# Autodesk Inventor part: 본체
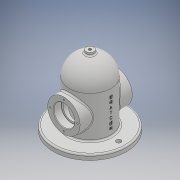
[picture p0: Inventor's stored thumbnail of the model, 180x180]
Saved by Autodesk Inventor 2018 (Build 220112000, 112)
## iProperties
Created: 2019-11
Part Number: 본체
Material: 일반
Document SubType Name: Modeling
Designer: USER
Density: 1 g/cm^3
Appearance: 기본값
Author: USER
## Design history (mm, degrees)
sketch "스케치3"
  geometry: C1 r 31 at (0, 0); 1 further point
  constraints: 1 centre point, 1 coincident
  dimensions: "d3" = 62 diameter of C1
extrude "돌출2" new body sketch "스케치3" stored distance "d4" = 100; taper "d5" = 0 deg
node "작업 평면1"
sketch "스케치5"
  geometry: C1 r 70 at (0, 0); 1 further point
  constraints: 1 centre point, 1 coincident
  dimensions: "d7" = 140 diameter of C1
extrude "돌출3" join sketch "스케치5" distance "d8" = 10; taper "d9" = 0 deg
sketch "스케치6"
  geometry: L1 (70, -40)-(-70, -40) reference; L2 (0, -40)-(-40, -40); L3 (-40, -40)-(-40, 40); L4 (-40, 40)-(0, 40); L5 (0, 40)-(0, -40); L6 (0, 40)-(0, 80); L7 (0, 40)-(-40, 40); L8 (0, 67.168)-(0, -67.168); 2 further points
  constraints: 14 end point, 3 midpoint, 2 horizontal, 2 parallel, 2 vertical, 1 perpendicular
  dimensions: "d10" = 80 distance of L2.end L3.end; "d11" = 40 distance of L3.end L4.end
revolve "회전1" sketch "스케치6" stored, may be unused: angle "d15" = 90 deg
sketch "스케치7"
  geometry: L1 (40, 40)-(-40, 40) reference; L2 (0, 82.045)-(0, -82.045); L3 (0, 40)-(-40, 40); L4 (0, 40)-(0, 80); A1 r 40 centre (0, 40) between (0, 80) and (-40, 40); 2 further points
  constraints: 6 end point, 2 midpoint, 2 point on circle, 2 point on line, 2 vertical, 1 centre point, 1 coincident, 1 horizontal
revolve "회전2" sketch "스케치7" stored, may be unused: angle "d16" = 90 deg
node "작업 평면2"
sketch "스케치8"
  geometry: C1 r 40 at (0, 0) reference; C2 r 7.5 at (0, 0); 1 further point
  constraints: 1 centre point, 1 coincident
  dimensions: "d18" = 15 diameter of C2
extrude "돌출4" join sketch "스케치8" stored distance "d19" = 10; taper "d20" = 0 deg
sketch "스케치9"
  geometry: C1 r 16.5 at (0, 0); 1 further point
  constraints: 1 centre point, 1 coincident
  dimensions: "d21" = 33 diameter of C1
extrude "돌출5" cut sketch "스케치9" extent not by distance; stored distance "d22" = 10; taper "d23" = 0 deg
sketch "스케치10"
  geometry: C1 r 20 at (0, 0); 1 further point
  constraints: 1 centre point, 1 coincident
  dimensions: "d24" = 40 diameter of C1
extrude "돌출6" cut sketch "스케치10" distance "d25" = 15; taper "d26" = 0 deg
sketch "스케치12"
  geometry: L1 (0, 40)-(-30, 40); L2 (-30, 40)-(-30, -50); L3 (-30, -50)-(0, -50); L4 (0, -50)-(0, 40); L5 (0, 126.817)-(0, -126.817); L6 (-70, -50)-(70, -50) reference; 2 further points
  constraints: 10 end point, 2 midpoint, 2 parallel, 1 coincident, 1 horizontal, 1 perpendicular, 1 vertical
  dimensions: "d37" = 30 distance of L1.start L1.end; "d38" = 90 distance of L1.end L2.end
revolve "회전3" sketch "스케치12" stored, may be unused: angle "d39" = 90 deg
sketch "스케치13"
  geometry: L1 (30, 40)-(-30, 40) reference; L2 (0, 40)-(0, 70); L3 (0, 40)-(-30, 40); L4 (0, 70)-(0, 40); L5 (0, 40)-(-30, 40); L6 (0, 99.673)-(0, -99.673); A1 r 30 centre (0, 40) between (0, 70) and (-30, 40); 2 further points
  constraints: 10 end point, 2 midpoint, 2 point on circle, 1 centre point, 1 coincident, 1 vertical
  dimensions: "d40" = 90 deg angle of L2 L3
revolve "회전4" sketch "스케치13" stored, may be unused: angle "d41" = 90 deg
sketch "스케치15"
  geometry: C1 r 7.5 at (0, 0) reference; C2 r 7.5 at (0, 0) reference; 2 further points
  constraints: 1 coincident
hole "구멍1" sketch "스케치15" at (0, 0) diameter "d42" = 5.188; stored, may be unused: countersink angle "d46" = 90 deg, drill point angle "d48" = 118 deg; dims "d43" = 30, "d44" = 4, "d45" = 2, "d47" = 30
sketch "스케치16"
  geometry: 2 further points
  constraints: 1 vertical alignment
  dimensions: "d49" = 26 distance of point (0, 0) point (0, 26)
hole "구멍2" sketch "스케치16" at (0, 26) diameter "d50" = 3.242; stored, may be unused: countersink angle "d54" = 90 deg, drill point angle "d56" = 118 deg; dims "d51" = 8, "d52" = 4, "d53" = 2, "d55" = 10
sketch "스케치17"
  geometry: C1 r 55 at (0, 0); C2 r 4.5 at (-55, 0); C3 r 4.5 at (55, 0); 1 further point
  constraints: 3 centre point, 2 horizontal alignment, 1 coincident
  dimensions: "d60" = 110 diameter of C1; "d61" = 9 diameter of C2; "d62" = 9 diameter of C3; "d63" = 55 distance of point (0, 0) C2.centre; "d64" = 55 distance of point (0, 0) C3.centre
extrude "돌출7" cut sketch "스케치17" distance "d65" = 15; taper "d66" = 0 deg
fillet "모깎기1" dims "d67" = 0.3
chamfer "모따기1" distance "d68" = 1; stored, may be unused: second distance "d69" = 2, angle "d70" = 45 deg
fillet "모깎기2" dims "d71" = 3
fillet "모깎기3" dims "d72" = 3
fillet "모깎기4" dims "d73" = 3
fillet "모깎기5" dims "d74" = 3
node "작업 평면3"
sketch "스케치19"
  geometry: L1 (-70, -50)-(70, -50) reference; 2 further points
  constraints: 1 coincident, 1 other
  dimensions: "d75" = 50 distance from line of L1 point (0, 0)
feature "엠보싱1" sketch "스케치19" dims "d5" = 0, "d76" = 0.5, "d77" = 0
node "솔리드2"
mirror "미러1"
pattern_circular "원형 패턴1" dims angle "d58" = 360 deg
mirror "미러2"
other parameters: "d17" = -135
